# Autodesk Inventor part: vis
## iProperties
Shininess: 88.0
Length Units: 11269
Angle Units: 11279
Time Units: 11290
Mass Units: 11283
Length Display Precision: 3
Angle Display Precision: 2
Created: 2002-06
Part Number: vis
Material: Par défaut
Document SubType Name: Modélisation
Designer: REVEST Pierre
Density: 1.0
Volumn: 97.02428855237847
Area: 269.77455390047453
PropertySet Name: Model Information
Control State: 0
Master: False
Checked Out: False
Author: REVEST Pierre
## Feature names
1. Révolution1 [Revolution]
2. Chanfrein1 [Chamfer]
3. Chanfrein2 [Chamfer]
4. Extrusion1
5. Révolution3 [Revolution]
